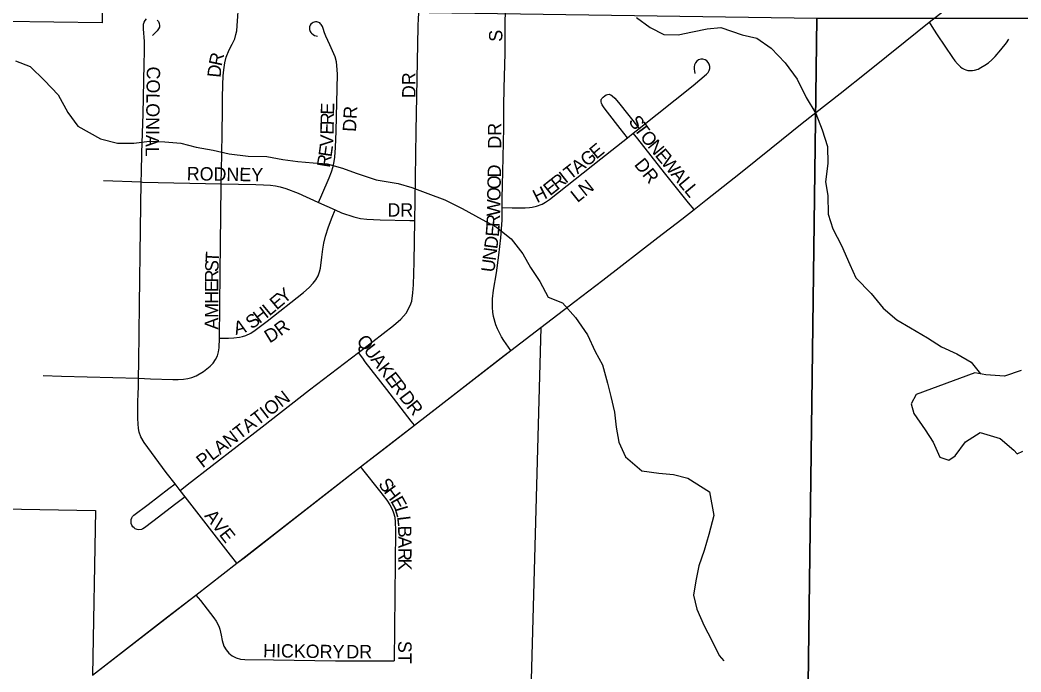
# Model space of a CAD drawing. Extents: x -97 to 34, y -21 to 22.
# Drawn here: x 4.03 to 4.741, y 18.009 to 18.471 of the extents above; entities that cross this region are included whole.
import ezdxf

# ---------------------------------------------------------------- set-up
doc = ezdxf.new("R2010")
doc.units = 0
for name, color, linetype in [('GM_X_City_Street', 7, 'Continuous'), ('GM_X_City_Street_Text', 7, 'Continuous'), ('GM_X_Corporation', 7, 'Continuous'), ('GM_X_Minor_Lake', 7, 'Continuous'), ('GM_X_Minor_River', 7, 'Continuous'), ('GM_X_Section', 7, 'Continuous'), ('GM_X_State_Route', 7, 'Continuous'), ('GM_X_Township_Subdivision', 7, 'Continuous'), ('GM_X_Township_Subdivision_Text', 7, 'Continuous')]:
    doc.layers.add(name, color=color, linetype=linetype)

msp = doc.modelspace()

# ---------------------------------------------------------------- linework, layer by layer
at = {"layer": 'GM_X_City_Street'}
for points in [[(4.17309, 18.35488), (4.1735, 18.37567), (4.17365, 18.39117), (4.17396, 18.4067), (4.17405, 18.4159), (4.1743, 18.42514), (4.17448, 18.43143), (4.1748, 18.4357), (4.17555, 18.44061), (4.17662, 18.44464), (4.17876, 18.44986), (4.18077, 18.45401), (4.18259, 18.45778), (4.1835, 18.4608), (4.18404, 18.46344), (4.18442, 18.46688), (4.18554, 18.48382), (4.18574, 18.48682)], [(4.31042, 18.32878), (4.31066, 18.34251), (4.31148, 18.39209), (4.31273, 18.46639), (4.31299, 18.47269), (4.31345, 18.47781), (4.31447, 18.48202)], [(4.37246, 18.33794), (4.3725, 18.3404), (4.37249, 18.34459), (4.37285, 18.36333), (4.37352, 18.39455), (4.37357, 18.41016), (4.37376, 18.42264), (4.37453, 18.44762), (4.3745, 18.45386), (4.3745, 18.46635), (4.37468, 18.47996)], [(4.11633, 18.35613), (4.11642, 18.36276), (4.11681, 18.37689), (4.11758, 18.40455), (4.11838, 18.43959), (4.1187, 18.44877), (4.1187, 18.45209), (4.11854, 18.45568), (4.11785, 18.46478), (4.11781, 18.46628), (4.11798, 18.46797), (4.11836, 18.46949), (4.11909, 18.47071), (4.12008, 18.47187)], [(4.12768, 18.47103), (4.12852, 18.46989), (4.12909, 18.46859), (4.1293, 18.46725), (4.12918, 18.46595), (4.12865, 18.46482), (4.12763, 18.46332), (4.12674, 18.46229), (4.12435, 18.46014)], [(4.24215, 18.34166), (4.24454, 18.34703), (4.24966, 18.35899), (4.25129, 18.36336), (4.2524, 18.36707), (4.25314, 18.37063), (4.25359, 18.37382), (4.25409, 18.38049), (4.25467, 18.39211), (4.25549, 18.43264), (4.25517, 18.43886), (4.25475, 18.44143), (4.25385, 18.44493), (4.25004, 18.45344), (4.24736, 18.45948), (4.2464, 18.46203), (4.2454, 18.465), (4.24483, 18.46644), (4.24403, 18.46778), (4.24359, 18.46835), (4.24297, 18.46895), (4.24233, 18.46933), (4.24161, 18.46956), (4.24082, 18.46969), (4.23999, 18.46971), (4.23908, 18.46961), (4.23838, 18.46937), (4.23749, 18.46884), (4.23658, 18.468), (4.23611, 18.46726), (4.23577, 18.46626), (4.2357, 18.46516), (4.23574, 18.46435), (4.2361, 18.46296), (4.23653, 18.46227), (4.23704, 18.4616), (4.23825, 18.46065), (4.23932, 18.46015), (4.24044, 18.45979), (4.24147, 18.4595)], [(4.6754, 18.46942), (4.67847, 18.46459), (4.68098, 18.46063), (4.69185, 18.44433), (4.69355, 18.44205), (4.69555, 18.43984), (4.6975, 18.43787), (4.69872, 18.43698), (4.70018, 18.43608), (4.70131, 18.4356), (4.70285, 18.43528), (4.70463, 18.43511), (4.70601, 18.4352), (4.70763, 18.43544), (4.71006, 18.43625), (4.71202, 18.43734), (4.71475, 18.43894), (4.71737, 18.44072), (4.71976, 18.44278), (4.7222, 18.44524), (4.72617, 18.44978), (4.73014, 18.45481), (4.73183, 18.45742)], [(4.46964, 18.3941), (4.50791, 18.42464), (4.51742, 18.43265), (4.51852, 18.43381), (4.51923, 18.43513), (4.51966, 18.43666), (4.51971, 18.43808), (4.51935, 18.43959), (4.51864, 18.44099), (4.51765, 18.4421), (4.51636, 18.44284), (4.5148, 18.44322), (4.51324, 18.44318), (4.51168, 18.44278), (4.51047, 18.4419), (4.50948, 18.44071), (4.50888, 18.43933), (4.50861, 18.43783), (4.50868, 18.43624), (4.50889, 18.4347), (4.50918, 18.43318)], [(4.46133, 18.38752), (4.4562, 18.39399), (4.44701, 18.40562), (4.44477, 18.40871), (4.44337, 18.41092), (4.44284, 18.41202), (4.44257, 18.41296), (4.44254, 18.41354), (4.4426, 18.41404), (4.44271, 18.41454), (4.44286, 18.41496), (4.44319, 18.41547), (4.44401, 18.41629), (4.44516, 18.41721), (4.44628, 18.41793), (4.44723, 18.41829), (4.44825, 18.41839), (4.44883, 18.4183), (4.44947, 18.418), (4.45052, 18.41727), (4.45221, 18.41549), (4.45482, 18.41252), (4.46964, 18.3941)], [(4.46133, 18.38752), (4.46543, 18.39079)], [(4.46543, 18.39079), (4.46964, 18.3941)], [(4.50855, 18.33659), (4.50469, 18.34137), (4.48748, 18.36271), (4.46866, 18.38667), (4.46543, 18.39079)], [(4.37246, 18.33794), (4.37941, 18.33789), (4.3887, 18.33783), (4.39185, 18.33801), (4.39356, 18.33824), (4.39667, 18.339), (4.40073, 18.3405), (4.40316, 18.3418), (4.40606, 18.34364), (4.44249, 18.3725), (4.46133, 18.38752)], [(4.08949, 18.35711), (4.11633, 18.35613)], [(4.11434, 18.21688), (4.11453, 18.22851), (4.11503, 18.2693), (4.11588, 18.32261), (4.11633, 18.35613)], [(4.11633, 18.35613), (4.1173, 18.35609), (4.17309, 18.35488)], [(4.17171, 18.24527), (4.17229, 18.29171), (4.17306, 18.35344), (4.17309, 18.35488)], [(4.17309, 18.35488), (4.19765, 18.35435), (4.20304, 18.35417), (4.20805, 18.3538), (4.21158, 18.35334), (4.21493, 18.35268), (4.21878, 18.35158), (4.22766, 18.34823), (4.24159, 18.34191), (4.24215, 18.34166)], [(4.24215, 18.34166), (4.25385, 18.33638)], [(4.37843, 18.23656), (4.37362, 18.24373), (4.37187, 18.24631), (4.37038, 18.24905), (4.3691, 18.2519), (4.368, 18.25482), (4.36626, 18.26081), (4.36572, 18.26389), (4.36544, 18.26699), (4.3655, 18.27323), (4.36615, 18.27944), (4.36825, 18.29176), (4.37002, 18.30412), (4.37147, 18.31653), (4.3723, 18.32898), (4.37246, 18.33794)], [(4.17171, 18.24527), (4.17831, 18.24546), (4.18193, 18.24562), (4.18609, 18.24599), (4.18824, 18.24644), (4.19045, 18.24726), (4.19394, 18.24896), (4.19713, 18.25104), (4.20558, 18.25741), (4.23152, 18.27773), (4.23545, 18.28122), (4.23833, 18.28436), (4.24021, 18.28682), (4.24172, 18.2895), (4.24287, 18.29232), (4.24345, 18.29508), (4.24442, 18.30287), (4.24508, 18.3085), (4.24574, 18.31265), (4.24703, 18.31764), (4.24922, 18.32422), (4.25186, 18.33115), (4.25385, 18.33638)], [(4.25385, 18.33638), (4.25834, 18.33435), (4.26724, 18.33137), (4.27187, 18.33022), (4.27648, 18.3297), (4.28582, 18.32919), (4.30699, 18.32884), (4.31042, 18.32878)], [(4.27037, 18.23524), (4.27318, 18.23735), (4.29529, 18.25437), (4.3006, 18.25886), (4.30417, 18.26301), (4.3072, 18.26857), (4.30818, 18.2715), (4.30912, 18.27761), (4.30945, 18.28324), (4.30991, 18.29926), (4.31042, 18.32878)], [(4.11434, 18.21688), (4.12295, 18.21658), (4.13873, 18.21607), (4.14242, 18.21612), (4.14627, 18.21627), (4.14942, 18.21675), (4.15219, 18.2175), (4.15522, 18.21857), (4.16045, 18.2216), (4.16522, 18.22545), (4.16728, 18.22763), (4.16902, 18.23014), (4.17038, 18.23288), (4.17108, 18.23565), (4.17151, 18.23854), (4.17171, 18.24527)], [(4.14384, 18.13736), (4.14895, 18.14136), (4.20199, 18.1825), (4.23578, 18.20861), (4.27037, 18.23524)], [(4.31007, 18.18358), (4.30783, 18.18649), (4.29048, 18.2089), (4.27526, 18.22866), (4.27347, 18.23108), (4.27037, 18.23524)], [(4.04677, 18.21894), (4.05972, 18.21842), (4.11434, 18.21688)], [(4.14032, 18.1419), (4.13392, 18.15012), (4.11836, 18.17131), (4.11602, 18.17531), (4.11481, 18.17856), (4.11427, 18.18133), (4.11404, 18.18464), (4.11388, 18.18826), (4.11385, 18.19241), (4.11391, 18.19664), (4.11395, 18.19967), (4.11411, 18.20642), (4.11426, 18.21027), (4.11434, 18.21688)], [(4.14741, 18.13276), (4.14092, 18.12784), (4.12458, 18.11519), (4.11857, 18.11076), (4.11736, 18.11008), (4.11639, 18.10969), (4.11469, 18.10944), (4.11344, 18.1096), (4.11207, 18.11014), (4.11119, 18.11078), (4.11043, 18.11157), (4.10961, 18.11275), (4.10925, 18.11392), (4.10912, 18.11479), (4.10924, 18.11669), (4.10961, 18.1178), (4.11015, 18.11874), (4.1111, 18.11974), (4.12112, 18.12733), (4.13596, 18.13859), (4.14032, 18.1419)], [(4.14384, 18.13736), (4.14032, 18.1419)], [(4.14741, 18.13276), (4.14384, 18.13736)], [(4.18409, 18.08562), (4.17952, 18.09148), (4.14741, 18.13276)]]:
    msp.add_lwpolyline(points, dxfattribs=at)
at = {"layer": 'GM_X_Corporation'}
msp.add_lwpolyline([(4.21143, 19.23497), (4.21247, 18.98027), (4.34537, 18.97923), (4.34272, 18.71668), (4.34187, 18.58447), (4.34039, 18.48025), (4.08888, 18.48872), (4.08862, 18.46907), (4.01991, 18.46997), (3.8361, 18.29087), (3.62811, 18.08996), (3.83338, 18.08773), (3.83374, 18.12765), (4.08374, 18.12321), (4.08167, 18.00637), (4.15504, 18.06314), (4.18409, 18.08562), (4.27193, 18.15399), (4.31007, 18.18358), (4.37843, 18.23656), (4.39993, 18.25302), (4.39223, 17.97714)], dxfattribs=at)
at = {"layer": 'GM_X_Minor_Lake'}
for points in [[(4.70767, 18.22068), (4.66622, 18.20547)], [(4.74059, 18.22239), (4.72881, 18.21842), (4.71559, 18.2194), (4.70767, 18.22068)], [(4.66622, 18.20547), (4.6627, 18.1987), (4.66448, 18.19185), (4.67261, 18.18033), (4.67813, 18.17152), (4.68288, 18.16082), (4.68927, 18.15881), (4.69385, 18.16177), (4.7012, 18.17188), (4.71152, 18.17853), (4.72581, 18.17411), (4.73551, 18.16598), (4.73773, 18.16329), (4.74192, 18.16511)]]:
    msp.add_lwpolyline(points, dxfattribs=at)
at = {"layer": 'GM_X_Minor_River'}
for points in [[(4.46759, 18.47279), (4.4773, 18.4658), (4.48705, 18.4607), (4.49725, 18.46052), (4.50749, 18.46262), (4.51773, 18.46472), (4.52758, 18.46569), (4.54262, 18.4605), (4.55316, 18.45804), (4.56326, 18.45105), (4.57329, 18.44064), (4.5818, 18.42911), (4.58801, 18.41612), (4.59501, 18.40462), (4.59935, 18.39317), (4.60332, 18.38135), (4.6035, 18.36921), (4.60177, 18.35635), (4.6035, 18.34646), (4.60366, 18.33319), (4.6069, 18.32289), (4.61313, 18.31103), (4.61896, 18.29766), (4.62334, 18.28811), (4.63412, 18.27693), (4.64264, 18.26654), (4.65234, 18.25841), (4.66207, 18.25256), (4.67406, 18.24553), (4.68416, 18.23929), (4.69504, 18.23417), (4.70515, 18.22831), (4.71183, 18.22001)], [(4.02703, 18.44209), (4.03755, 18.43812), (4.04759, 18.42809), (4.05726, 18.41806), (4.06423, 18.40543), (4.07126, 18.39583), (4.08737, 18.38683), (4.09941, 18.38359), (4.11114, 18.38377), (4.12212, 18.38509), (4.13307, 18.38453), (4.1444, 18.38357), (4.15532, 18.38073), (4.16738, 18.37863), (4.17868, 18.37616), (4.19226, 18.37441), (4.20549, 18.37418), (4.2168, 18.37209), (4.22736, 18.37077), (4.23831, 18.36982), (4.24812, 18.36889), (4.25904, 18.36605), (4.26881, 18.36247), (4.2831, 18.35767), (4.29856, 18.35513), (4.30834, 18.35231), (4.31961, 18.34795), (4.33164, 18.34357), (4.34401, 18.33729), (4.35825, 18.32946), (4.36836, 18.32398), (4.37881, 18.31583), (4.38696, 18.30508), (4.39247, 18.2955), (4.39911, 18.28553), (4.40498, 18.27443), (4.41512, 18.27047), (4.4244, 18.26007), (4.43289, 18.24779), (4.43837, 18.23594), (4.44351, 18.22637), (4.44708, 18.21342), (4.44956, 18.2039), (4.45203, 18.19286), (4.45337, 18.18222), (4.45509, 18.17157), (4.45983, 18.16125), (4.47138, 18.1512), (4.48345, 18.14947), (4.49402, 18.14853), (4.50419, 18.14608), (4.51953, 18.13634), (4.52266, 18.1196)], [(4.52266, 18.1196), (4.51904, 18.10601), (4.51583, 18.09469), (4.51187, 18.08377), (4.5098, 18.07318), (4.50812, 18.06298), (4.51061, 18.05307), (4.5157, 18.04123), (4.52084, 18.03129), (4.52633, 18.02019), (4.52966, 18.01635)]]:
    msp.add_lwpolyline(points, dxfattribs=at)
at = {"layer": 'GM_X_Section'}
for points in [[(3.5921, 18.48713), (4.59557, 18.47233), (4.58268, 17.47301), (3.57953, 17.47948)], [(4.59557, 18.47233), (5.59082, 18.47236), (5.58508, 17.4654), (4.58268, 17.47301)]]:
    msp.add_lwpolyline(points, close=True, dxfattribs=at)
at = {"layer": 'GM_X_State_Route'}
for points in [[(4.39992, 18.25302), (4.42389, 18.27136), (4.4438, 18.2864), (4.48292, 18.31666), (4.49986, 18.32977), (4.50855, 18.33659), (4.517, 18.34323), (4.54141, 18.36266), (4.56334, 18.38016), (4.58536, 18.39776), (4.61228, 18.41885), (4.63177, 18.43439), (4.6584, 18.45571), (4.6754, 18.46942), (4.68492, 18.47676)], [(4.08167, 18.00636), (4.13503, 18.04765), (4.15504, 18.06314), (4.18409, 18.08562), (4.18922, 18.0896), (4.22849, 18.12031), (4.25561, 18.14126), (4.27193, 18.15399), (4.29, 18.16809), (4.31007, 18.18358), (4.32701, 18.19665), (4.37376, 18.23298), (4.37843, 18.23656), (4.39992, 18.25302)]]:
    msp.add_lwpolyline(points, dxfattribs=at)
at = {"layer": 'GM_X_Township_Subdivision'}
for points in [[(4.27193, 18.15399), (4.27332, 18.15225), (4.28534, 18.13715), (4.29048, 18.13038), (4.29259, 18.127), (4.29432, 18.12398), (4.29537, 18.12143), (4.29612, 18.11842), (4.29645, 18.11487), (4.29665, 18.1091), (4.29578, 18.01639)], [(4.15504, 18.06314), (4.15823, 18.05914), (4.16785, 18.04707), (4.16944, 18.04454), (4.17139, 18.04107), (4.17215, 18.03886), (4.173, 18.03457), (4.17374, 18.03084), (4.17491, 18.02691), (4.17651, 18.0242), (4.17842, 18.0218), (4.1809, 18.01996), (4.18367, 18.01862), (4.18663, 18.01773), (4.18976, 18.01749), (4.21024, 18.01705), (4.25423, 18.01655), (4.27586, 18.01649), (4.29578, 18.01639)]]:
    msp.add_lwpolyline(points, dxfattribs=at)

# ---------------------------------------------------------------- texts
at = {"layer": 'GM_X_City_Street_Text'}
for s, rotation, p in [('S', 90, (4.37254, 18.45561)), ('R', 78.0613, (4.17333, 18.43788)), ('COLONIAL', 269.1935, (4.12028, 18.43809)), ('D', 84.35246, (4.17255, 18.42986)), ('DR', 90, (4.31088, 18.41561)), ('E', 88.63411, (4.2531, 18.4038)), ('DR', 86.98901, (4.26864, 18.39153)), ('R', 88.63487, (4.25292, 18.3963)), ('S', 305.64568, (4.46161, 18.39915)), ('E', 88.63272, (4.25276, 18.38964)), ('DR', 90, (4.37171, 18.37978)), ('T', 306.14938, (4.46555, 18.39365)), ('V', 87.26044, (4.25236, 18.38107)), ('O', 308.72192, (4.46977, 18.38791)), ('E', 81.80334, (4.25131, 18.37351)), ('E', 39.69401, (4.43925, 18.37188)), ('N', 309.58389, (4.47508, 18.38128)), ('R', 80.70538, (4.25007, 18.36592)), ('G', 38.22613, (4.4325, 18.36655)), ('DR', 308.65626, (4.46564, 18.36833)), ('E', 309.62123, (4.48039, 18.37485)), ('W', 309.59462, (4.48464, 18.36972)), ('RODNEY', 359.01282, (4.14852, 18.3574)), ('D', 88.8634, (4.37147, 18.35926)), ('T', 38.20326, (4.42071, 18.35727)), ('A', 38.22613, (4.42595, 18.3614)), ('O', 88.88525, (4.37131, 18.35092)), ('R', 38.23498, (4.41154, 18.35005)), ('I', 38.21614, (4.41743, 18.35469)), ('A', 309.58166, (4.49155, 18.36137)), ('L', 309.6038, (4.49686, 18.35494)), ('H', 26.81913, (4.39712, 18.341)), ('E', 38.57631, (4.40635, 18.3459)), ('LN', 38.66336, (4.42578, 18.34109)), ('L', 309.60271, (4.50111, 18.34981)), ('O', 88.88931, (4.37114, 18.34259)), ('DR', 0.00001, (4.291, 18.33156)), ('W', 88.69389, (4.3709, 18.33173)), ('R', 87.28455, (4.37053, 18.32398)), ('E', 85.62159, (4.37, 18.31703)), ('D', 82.66582, (4.36889, 18.30824)), ('T', 87.02023, (4.17127, 18.29881)), ('N', 82.56388, (4.36781, 18.29996)), ('S', 87.51281, (4.17098, 18.29217)), ('U', 82.54691, (4.36673, 18.29169)), ('R', 89.31995, (4.17089, 18.28475)), ('E', 89.97267, (4.17089, 18.27811)), ('Y', 40.03227, (4.2175, 18.26927)), ('H', 89.97813, (4.17089, 18.26978)), ('E', 40.03441, (4.2124, 18.26498)), ('M', 89.98178, (4.17089, 18.25978)), ('H', 37.26609, (4.20023, 18.25538)), ('L', 39.54842, (4.20719, 18.26068)), ('A', 89.97813, (4.17088, 18.25145)), ('S', 36.00342, (4.19466, 18.25133)), ('A', 15.6212, (4.18334, 18.24749)), ('D', 31.6347, (4.20735, 18.24154)), ('R', 37.04029, (4.21523, 18.24645)), ('Q', 307.1715, (4.2686, 18.24331)), ('U', 307.17111, (4.27363, 18.23667)), ('A', 307.17111, (4.27867, 18.23003)), ('K', 307.1715, (4.2837, 18.22338)), ('E', 307.16694, (4.28874, 18.21674)), ('R', 307.16136, (4.29277, 18.21143)), ('PLANTATION', 37.64622, (4.15991, 18.15286)), ('D', 307.18694, (4.29881, 18.20346)), ('R', 308.28155, (4.30396, 18.19666)), ('AVE', 308.05089, (4.16073, 18.11921))]:
    msp.add_text(s, height=0.00947, rotation=rotation, dxfattribs=at).set_placement(p)
at = {"layer": 'GM_X_Township_Subdivision_Text'}
for s, rotation, p in [('S', 306.624, (4.28408, 18.14169)), ('H', 306.62513, (4.28806, 18.13634)), ('E', 299.0095, (4.29285, 18.12993)), ('L', 286.8275, (4.29588, 18.12459)), ('L', 276.87425, (4.29772, 18.11864)), ('B', 270.85003, (4.2985, 18.11228)), ('A', 270, (4.29861, 18.10482)), ('R', 269.99405, (4.29861, 18.09649)), ('K', 269.99284, (4.29861, 18.08899)), ('HICKORY', 359.07647, (4.20269, 18.01906)), ('DR', 0.00001, (4.26183, 18.01823)), ('ST', 270, (4.29861, 18.03062))]:
    msp.add_text(s, height=0.00947, rotation=rotation, dxfattribs=at).set_placement(p)

doc.saveas('drawing.dxf')
